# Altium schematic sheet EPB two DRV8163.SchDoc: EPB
size A4; Date: Not shown in title block; ApprovedBy: Hely Zhang; CheckedBy: Not shown in title block; Author: Not shown in title block; CompanyName: Not shown in title block; DrawnBy: Hely Zhang; Engineer: Not shown in title block; Organization: Not shown in title block; Address1: Not shown in title block; Address2: Not shown in title block; Address3: Not shown in title block; Address4: Not shown in title block; DocumentNumber: 1; Revision: Use project parameter SCH_Rev; SheetNumber: 7; SheetTotal: 14; PageSetup: Record=PageOptions¦CenterHorizontal=True¦CenterVertical=True¦PrintScale=0.93¦XCorrection=1.00¦YCorrection=1.00¦PrintKind=0¦BorderSize=5000000¦LeftOffset=0¦BottomOffset=0¦Orientation=2¦PaperLength=1000¦PaperWidth=1000¦Scale=100¦PaperSource=15¦PrintQuality=600¦MediaType=1¦DitherType=10¦PaperKind=Letter¦PrintScaleMode=1
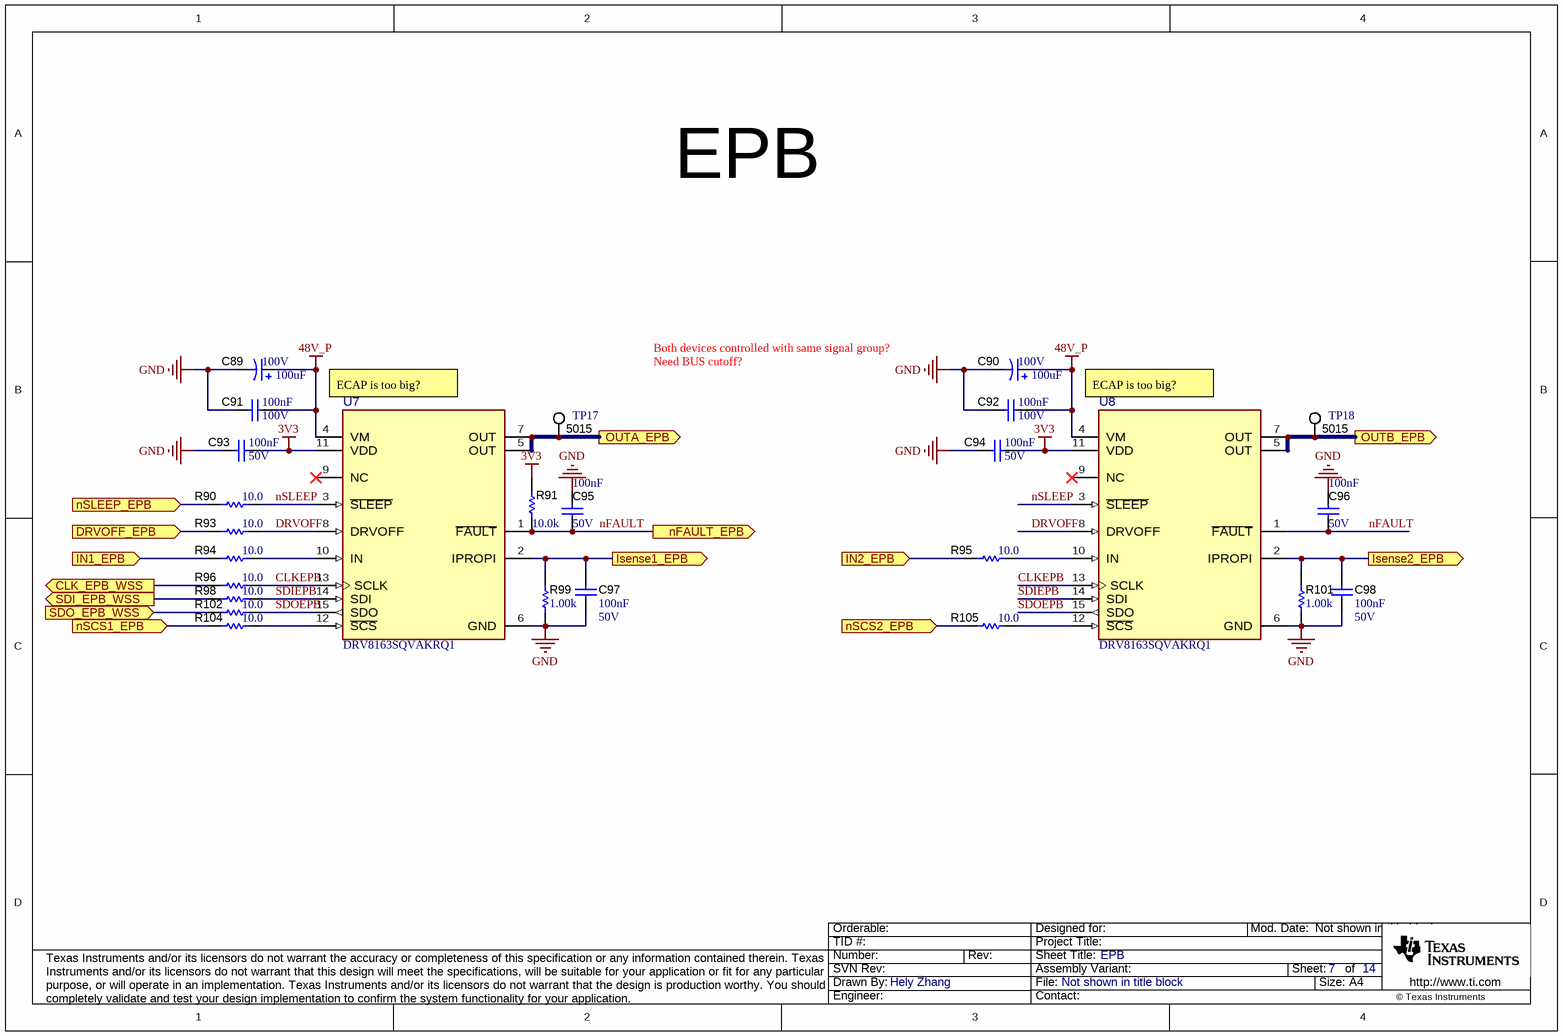
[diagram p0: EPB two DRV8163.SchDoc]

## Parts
C89  VDC_V: 100V  ValueDisplayed: 100uF  [SM_RADIAL_J16]  (hidden comment: EEV-FK2A101M)
C90  VDC_V: 100V  ValueDisplayed: 100uF  [SM_RADIAL_J16]  (hidden comment: EEV-FK2A101M)
C91  Cap_F: 100nF  VDC_V: 100V  [0603]  (hidden comment: HMK107B7104KAHT)
C92  Cap_F: 100nF  VDC_V: 100V  [0603]  (hidden comment: HMK107B7104KAHT)
C93  Cap_F: 100nF  VDC_V: 50V  [0603]  (hidden comment: GCM188R71H104KA57D)
C94  Cap_F: 100nF  VDC_V: 50V  [0603]  (hidden comment: GCM188R71H104KA57D)
C95  Cap_F: 100nF  VDC_V: 50V  [0603]  (hidden comment: GCM188R71H104KA57D)
C96  Cap_F: 100nF  VDC_V: 50V  [0603]  (hidden comment: GCM188R71H104KA57D)
C97  Cap_F: 100nF  VDC_V: 50V  [0603]  (hidden comment: GCM188R71H104KA57D)
C98  Cap_F: 100nF  VDC_V: 50V  [0603]  (hidden comment: GCM188R71H104KA57D)
R90  ValueDisplayed: 10.0  [0603]  (hidden comment: RC0603FR-0710RL)
R91  ValueDisplayed: 10.0k  [0603]  (hidden comment: RC0603FR-0710KL)
R93  ValueDisplayed: 10.0  [0603]  (hidden comment: RC0603FR-0710RL)
R94  ValueDisplayed: 10.0  [0603]  (hidden comment: RC0603FR-0710RL)
R95  ValueDisplayed: 10.0  [0603]  (hidden comment: RC0603FR-0710RL)
R96  ValueDisplayed: 10.0  [0603]  (hidden comment: RC0603FR-0710RL)
R98  ValueDisplayed: 10.0  [0603]  (hidden comment: RC0603FR-0710RL)
R99  ValueDisplayed: 1.00k  [0603]  (hidden comment: RC0603FR-071KL)
R101  ValueDisplayed: 1.00k  [0603]  (hidden comment: RC0603FR-071KL)
R102  ValueDisplayed: 10.0  [0603]  (hidden comment: RC0603FR-0710RL)
R104  ValueDisplayed: 10.0  [0603]  (hidden comment: RC0603FR-0710RL)
R105  ValueDisplayed: 10.0  [0603]  (hidden comment: RC0603FR-0710RL)
TP17  5015  [Testpoint_Keystone_Miniature]
TP18  5015  [Testpoint_Keystone_Miniature]
U7  DRV8163SQVAKRQ1  [VAK0015A-MFG]
U8  DRV8163SQVAKRQ1  [VAK0015A-MFG]

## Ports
CLK_EPB_WSS (out), DRVOFF_EPB (in), IN1_EPB (in), IN2_EPB (in), Isense1_EPB (out), Isense2_EPB (out), nFAULT_EPB (out), nSCS1_EPB (in), nSCS2_EPB (in), nSLEEP_EPB (in), OUTA_EPB (out), OUTB_EPB (out), SDI_EPB_WSS (out), SDO_EPB_WSS (in)

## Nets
3V3: C93.1 C94.1 R91.2 U7.11(VDD) U8.11(VDD)
48V_P: C89.1(+) C90.1(+) C91.2 C92.2 U7.4(VM) U8.4(VM)
GND: C89.2(-) C90.2(-) C91.1 C92.1 C93.2 C94.2 C95.2 C96.2 C97.2 C98.2 R99.2 R101.2 U7.6(GND) U8.6(GND)
CLK_EPB_WSS: R96.1 ; port CLK_EPB_WSS
CLKEPB: R96.2 U7.13(SCLK) U8.13(SCLK)
DRVOFF: R93.2 U7.8(DRVOFF) U8.8(DRVOFF)
DRVOFF_EPB: R93.1 ; port DRVOFF_EPB
IN1_EPB: R94.1 ; port IN1_EPB
IN2_EPB: R95.1 ; port IN2_EPB
Isense1_EPB: C97.1 R99.1 U7.2(IPROPI) ; port Isense1_EPB
Isense2_EPB: C98.1 R101.1 U8.2(IPROPI) ; port Isense2_EPB
nFAULT: C95.1 C96.1 R91.1 U7.1(~{FAULT}) U8.1(~{FAULT}) ; port nFAULT_EPB
nSCS1_EPB: R104.1 ; port nSCS1_EPB
nSCS2_EPB: R105.1 ; port nSCS2_EPB
nSLEEP: R90.2 U7.3(~{SLEEP}) U8.3(~{SLEEP})
nSLEEP_EPB: R90.1 ; port nSLEEP_EPB
OUTA_EPB: TP17.1 U7.5(OUT) U7.7(OUT) ; port OUTA_EPB
OUTB_EPB: TP18.1 U8.5(OUT) U8.7(OUT) ; port OUTB_EPB
SDI_EPB_WSS: R98.1 ; port SDI_EPB_WSS
SDIEPB: R98.2 U7.14(SDI) U8.14(SDI)
SDO_EPB_WSS: R102.1 ; port SDO_EPB_WSS
SDOEPB: R102.2 U7.15(SDO) U8.15(SDO)
NetR94_2: R94.2 U7.10(IN)
NetR95_2: R95.2 U8.10(IN)
NetR104_2: R104.2 U7.12(~{SCS})
NetR105_2: R105.2 U8.12(~{SCS})

Not connected (* = marked no-connect by the designer): U7 9(NC)*; U8 9(NC)*

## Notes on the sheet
- EPB
- Both devices controlled with same signal group?
- Need BUS cutoff?
- (near U7) ECAP is too big?
- (near U8) ECAP is too big?

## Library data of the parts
C89 C90 = CMP-0011221-1: CAP, AL, 100 uF, 100 V, +/- 20%, 0.17 ohm, AEC-Q200 Grade 2, SMD; Manufacturer: Panasonic; TaMin_C: -55°C; ESR_ohm: 0.17; Polarized: Y; SizeAreaWB_mm2: 399; U/M: EA; Value: 100uF; TaMax_C: 105°C; SizeZ_mm: 16.5; SizeX_mm: 19; SizeY_mm: 17; Cap_Case: J16; SizeArea_mm2: 323; CompType: Capacitor; Cap_F: 100µF; IRMS_A: 793mA; AEC Grade: 2; AEC Category: Q200
C91 C92 = CMP-0081011-1: CAP, CERM, 0.1 µF, 100 V,+/- 10%, X7R, AEC-Q200 Grade 1, 0603; Manufacturer: Taiyo Yuden; SizeAreaWB_mm2: 4.68; SizeArea_mm2: 1.28; AEC Qualified: Y; AEC Category: Q200; Value: 0.1uF; TaMax_C: 125°C; SizeZ_mm: 1; Polarized: N; TaMin_C: -55°C; SizeY_mm: 0.8; U/M: EA; SizeX_mm: 1.6; ValueDisplayed: 0.1µF
C93-C98 = CMP-0007144-1: CAP, CERM, 0.1 uF, 50 V, +/- 10%, X7R, 0603; Manufacturer: MuRata; TaMin_C: -55°C; ESR_ohm: 20m; Polarized: N; SizeAreaWB_mm2: 4.68; Value1: 0.02 ohm; U/M: EA; Value: 0.1uF; TaMax_C: 125°C; SizeZ_mm: 1; SizeX_mm: 1.6; SizeY_mm: 0.8; SizeArea_mm2: 1.28; IRMS_A: 1.84A; AEC Category: Q200
R90 R93-R96 R98 R102 R104 R105 = CMP-0022751-4: RES, 10.0, 1%, 0.1 W, 0603; Manufacturer: Yageo; Power_W: 100mW; TempCo: 100 ppm/C; Value_Code: 10R0; Value: 10.0; EIA_Code: E96; Res_ohm: 10; SizeX_mm: 1.6; SizeY_mm: 0.8; SizeZ_mm: 1; Value2: 0.1W; SizeArea_mm2: 1.28; AEC Qualified: N; VDC_V: 75V; AEC Category: Q200; SizeAreaWB_mm2: 4.68
R91 = CMP-0022746-5: RES, 10.0 k, 1%, 0.1 W, 0603; Manufacturer: Yageo; Power_W: 100mW; TempCo: 100 ppm/C; Value_Code: 10k0; Value: 10.0k; EIA_Code: E96; Res_ohm: 10k; SizeX_mm: 1.6; SizeY_mm: 0.8; SizeZ_mm: 1; Value2: 0.1W; SizeArea_mm2: 1.28; AEC Qualified: N; VDC_V: 75V; AEC Category: Q200; SizeAreaWB_mm2: 4.68
R99 R101 = CMP-0022895-5: RES, 1.00 k, 1%, 0.1 W, 0603; Manufacturer: Yageo; Power_W: 100mW; TempCo: 100 ppm/C; Value_Code: 1k00; Value: 1.00k; EIA_Code: E96; Res_ohm: 1k; SizeX_mm: 1.6; SizeY_mm: 0.8; SizeZ_mm: 1; Value2: 0.1W; SizeArea_mm2: 1.28; AEC Qualified: N; VDC_V: 75V; AEC Category: Q200; SizeAreaWB_mm2: 4.68
TP17 TP18 = CMP-0055152-1: Test Point, Miniature, SMT; Manufacturer: Keystone; CNHeader: FALSE; Green_Lifecycle: Active; Green_REACh: Passed; CT: TRUE
U7 U8 = CMP-0123332-2: Automotive 65-V H-Bridge Driver with Integrated Current Sense and Diagnostics; Manufacturer: Texas Instruments; SizeZ_mm: 1mm; AEC Qualified: Yes; AEC Grade: Grade 1; Max Supply Voltage: 65V; Min Supply Voltage: 3V; Motor Type: Brushed; Nominal Supply Current: 3mA; Number Of Outputs: 1; Standoff Height: 0mm; Switching Frequency: 0-100kHz; TaMax_C: +125°C; TaMin_C: -40°C; TJmax_C: +150°C; AEC Category: Q200; CompType: IC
